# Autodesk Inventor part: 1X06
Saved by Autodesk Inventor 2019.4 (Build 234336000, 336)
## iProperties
Created: 2020-03
Part Number: 1X06
Material: Generic
Document SubType Name: Modeling
Designer: Administrator
Density: 1 g/cm^3
Appearance: Default
Title: 1X06
Author: Administrator
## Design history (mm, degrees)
feature "Body2"
body "Solid1"
